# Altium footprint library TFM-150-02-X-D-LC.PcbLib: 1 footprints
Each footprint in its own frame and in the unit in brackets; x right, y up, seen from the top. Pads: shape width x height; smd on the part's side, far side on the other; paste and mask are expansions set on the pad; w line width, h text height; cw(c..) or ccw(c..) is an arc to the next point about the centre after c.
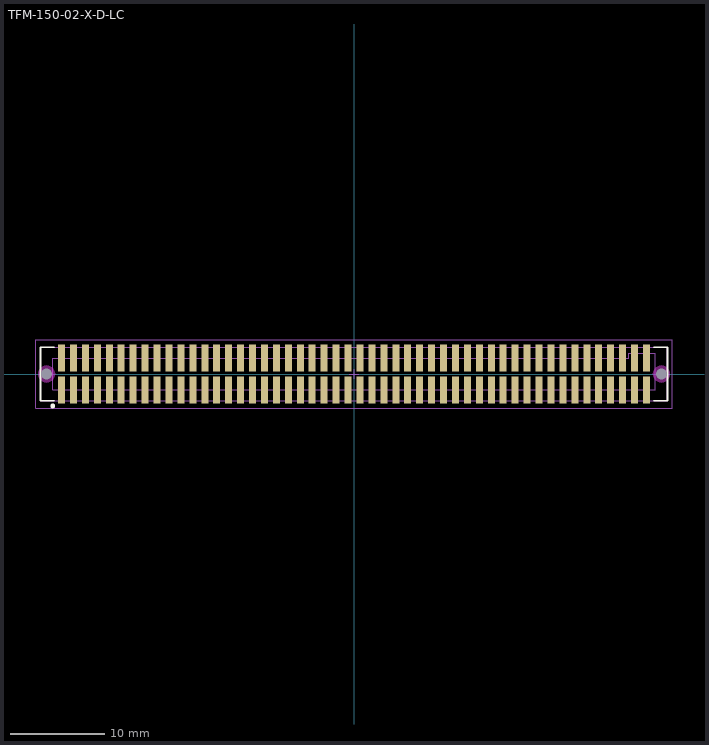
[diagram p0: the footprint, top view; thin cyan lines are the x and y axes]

## TFM-150-02-X-D-LC [mm] "1.27mm pitch, 100 pin, terminal strip; w/locking clips, SMT"
height 5.72
pads (102):
  rect 0.75x2.9 smd mask+0: 1(-31.115,-1.714) 2(-31.115,1.714) 3(-29.845,-1.714) 4(-29.845,1.714) 5(-28.575,-1.714) 6(-28.575,1.714) 7(-27.305,-1.714) 8(-27.305,1.714) 9(-26.035,-1.714) 10(-26.035,1.714) 11(-24.765,-1.714) 12(-24.765,1.714) 13(-23.495,-1.714) 14(-23.495,1.714) 15(-22.225,-1.714) 16(-22.225,1.714) 17(-20.955,-1.714) 18(-20.955,1.714) 19(-19.685,-1.714) 20(-19.685,1.714) 21(-18.415,-1.714) 22(-18.415,1.714) 23(-17.145,-1.714) 24(-17.145,1.714) 25(-15.875,-1.714) 26(-15.875,1.714) 27(-14.605,-1.714) 28(-14.605,1.714) 29(-13.335,-1.714) 30(-13.335,1.714) 31(-12.065,-1.714) 32(-12.065,1.714) 33(-10.795,-1.714) 34(-10.795,1.714) 35(-9.525,-1.714) 36(-9.525,1.714) 37(-8.255,-1.714) 38(-8.255,1.714) 39(-6.985,-1.714) 40(-6.985,1.714) 41(-5.715,-1.714) 42(-5.715,1.714) 43(-4.445,-1.714) 44(-4.445,1.714) 45(-3.175,-1.714) 46(-3.175,1.714) 47(-1.905,-1.714) 48(-1.905,1.714) 49(-0.635,-1.714) 50(-0.635,1.714) 51(0.635,-1.714) 52(0.635,1.714) 53(1.905,-1.714) 54(1.905,1.714) 55(3.175,-1.714) 56(3.175,1.714) 57(4.445,-1.714) 58(4.445,1.714) 59(5.715,-1.714) 60(5.715,1.714) 61(6.985,-1.714) 62(6.985,1.714) 63(8.255,-1.714) 64(8.255,1.714) 65(9.525,-1.714) 66(9.525,1.714) 67(10.795,-1.714) 68(10.795,1.714) 69(12.065,-1.714) 70(12.065,1.714) 71(13.335,-1.714) 72(13.335,1.714) 73(14.605,-1.714) 74(14.605,1.714) 75(15.875,-1.714) 76(15.875,1.714) 77(17.145,-1.714) 78(17.145,1.714) 79(18.415,-1.714) 80(18.415,1.714) 81(19.685,-1.714) 82(19.685,1.714) 83(20.955,-1.714) 84(20.955,1.714) 85(22.225,-1.714) 86(22.225,1.714) 87(23.495,-1.714) 88(23.495,1.714) 89(24.765,-1.714) 90(24.765,1.714) 91(26.035,-1.714) 92(26.035,1.714) 93(27.305,-1.714) 94(27.305,1.714) 95(28.575,-1.714) 96(28.575,1.714) 97(29.845,-1.714) 98(29.845,1.714) 99(31.115,-1.714) 100(31.115,1.714)
  round 1 hole 1.2 unplated mask+0: 101(-32.703,0) 102(32.703,0)
Top Overlay:
  circle w0.25: c-32.05,-3.4 r0.125
  lines w0.2: -31.9,-2.85 -33.35,-2.85 -33.35,2.85 -31.9,2.85 ; 31.9,-2.85 33.35,-2.85 33.35,2.85 31.9,2.85
Keep-Out Layer:
  pour cut-out: 33.61,0 33.58,0.235 33.489,0.454 33.345,0.642 33.157,0.786 32.938,0.877 32.703,0.908 32.468,0.877 32.249,0.786 32.061,0.642 31.917,0.454 31.826,0.235 31.795,0 31.826,-0.235 31.917,-0.454 32.061,-0.642 32.249,-0.786 32.468,-0.877 32.703,-0.908 32.938,-0.877 33.157,-0.786 33.345,-0.642 33.489,-0.454 33.58,-0.235
  pour cut-out: -31.795,0 -31.826,0.235 -31.917,0.454 -32.061,0.642 -32.249,0.786 -32.468,0.877 -32.703,0.908 -32.938,0.877 -33.157,0.786 -33.345,0.642 -33.489,0.454 -33.58,0.235 -33.61,0 -33.58,-0.235 -33.489,-0.454 -33.345,-0.642 -33.157,-0.786 -32.938,-0.877 -32.703,-0.908 -32.468,-0.877 -32.249,-0.786 -32.061,-0.642 -31.917,-0.454 -31.826,-0.235
Mechanical 12:
  lines w0.001: -33.35,-2.85 -33.35,2.85 33.35,2.85 33.35,-2.85 -33.35,-2.85 ; -32.05,-1.7 -32.05,1.7 29.25,1.7 29.25,2.2 32.05,2.2 32.05,-1.7 -32.05,-1.7
Mechanical 13:
  circle w0.1: c-32.027,-3.373 r0.127
  lines w0.1: -33.35,-2.85 -33.35,2.85 33.35,2.85 33.35,-2.85 -33.35,-2.85 ; -32.05,-1.7 -32.05,1.7 29.25,1.7 29.25,2.2 32.05,2.2 32.05,-1.7 -32.05,-1.7
  text ".Designator" at 0,-0.127 h1.52
Mechanical 15:
  lines w0.05: -0.5,0 0.5,0 ; 0,-0.5 0,0.5 ; -33.85,-3.65 -33.85,3.65 33.85,3.65 33.85,-3.65 -33.85,-3.65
